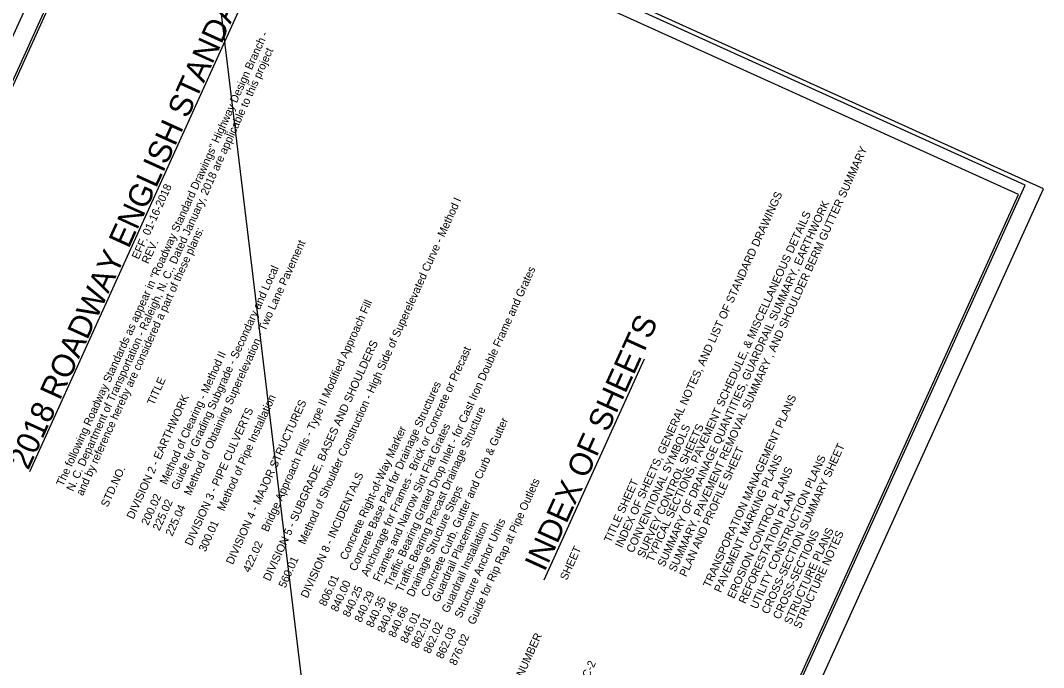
# Model space of a CAD drawing. Extents: x 1744741 to 2014229, y 466994 to 951338.
# Drawn here: x 2007510 to 2010026, y 477236 to 478827 of the extents above; entities that cross this region are included whole.
import ezdxf

# ---------------------------------------------------------------- set-up
doc = ezdxf.new("R2010")
doc.units = 0
for name, color, linetype in [('Old_Level_1', 7, 'Continuous'), ('Prop Guardrail Anchor Unit CELL', 7, 'Continuous'), ('Sheet Data Text CELL', 7, 'Continuous'), ('Sheet Plan CELL', 7, 'Continuous'), ('Sheet Plot Border Inside CELL', 7, 'Continuous'), ('Sheet Plot Border Outside CELL', 7, 'Continuous'), ('Sheet Sticker Preliminary CELL', 7, 'Continuous')]:
    doc.layers.add(name, color=color, linetype=linetype)

msp = doc.modelspace()

# ---------------------------------------------------------------- linework, layer by layer
at = {"layer": 'Old_Level_1'}
for p, q in [((2007533.4, 477718), (2008139.4, 479055)), ((2008798.2, 477452.1), (2009044.4, 477995.4))]:
    msp.add_line(p, q, dxfattribs=at)
at = {"layer": 'Prop Guardrail Anchor Unit CELL'}
msp.add_line((2008573.3, 474121.5), (2007740.2, 481039.5), dxfattribs=at)
at = {"layer": 'Sheet Plan CELL'}
msp.add_lwpolyline([(2007812, 479374.1), (2006418.7, 476300.1), (2008570.5, 475324.8), (2009963.8, 478398.8)], close=True, dxfattribs=at)
at = {"layer": 'Sheet Plot Border Inside CELL'}
msp.add_lwpolyline([(2008433, 475007.9), (2009980.5, 478422.1), (2007818.5, 479402), (2006271, 475987.9)], close=True, dxfattribs=at)
at = {"layer": 'Sheet Plot Border Outside CELL'}
msp.add_lwpolyline([(2008462, 474962.7), (2010025.7, 478412.7), (2007781.7, 479429.8), (2006218, 475979.8)], close=True, dxfattribs=at)

# ---------------------------------------------------------------- texts
at = {"layer": 'Old_Level_1'}
for s, height, p in [('422.02    Bridge Approach Fills - Type II Modified Approach Fill', 19.688, (2008073.7, 477468.1)), ('INDEX OF SHEETS', 56.25, (2008799, 477469.8)), ('DIVISION 4 - MAJOR STRUCTURES', 19.688, (2008032.4, 477487.7))]:
    msp.add_text(s, height=height, rotation=65.6171, dxfattribs=at).set_placement(p)
at = {"layer": 'Sheet Data Text CELL'}
for s, p in [('SUMMARY, PAVEMENT REMOVAL SUMMARY , AND SHOULDER BERM GUTTER SUMMARY', (2009120.8, 477469.4)), ('INDEX OF SHEETS, GENERAL NOTES, AND LIST OF STANDARD DRAWINGS', (2008989.3, 477529)), ('SUMMARY OF DRAINAGE QUANTITIES, GUARDRAIL SUMMARY, EARTHWORK ', (2009093.3, 477481.8)), ('TYPICAL SECTIONS, PAVEMENT SCHEDULE, & MISCELLANEOUS DETAILS', (2009065.5, 477494.4)), ('TRANSPORATION MANAGEMENT PLANS', (2009205.5, 477431)), ('CONVENTIONAL SYMBOLS ', (2009016.8, 477516.5)), ('SURVEY CONTROL SHEETS', (2009043.5, 477504.4)), ('PLAN AND PROFILE SHEET', (2009147.1, 477457.5)), ('CROSS-SECTION SUMMARY SHEET', (2009349.2, 477365.9)), ('PAVEMENT MARKING PLANS', (2009232.4, 477418.8)), ('UTILITY CONSTRUCTION PLANS', (2009321.5, 477378.4)), ('EROSION CONTROL PLANS', (2009264.8, 477404.1)), ('TITLE SHEET', (2008961.8, 477541.5)), ('REFORESTATION PLAN', (2009292.8, 477391.4)), ('STRUCTURE PLANS', (2009404.5, 477340.8)), ('CROSS-SECTIONS', (2009377, 477353.2)), ('STRUCTURE NOTES', (2009427.8, 477330.2)), ('SHEET NUMBER                    SHEET   ', (2008706.8, 477125.2)), ('1C-1 THRU 1C-2', (2008842.3, 477063.8))]:
    msp.add_text(s, height=19.688, rotation=65.6171, dxfattribs=at).set_placement(p)
at = {"layer": 'Sheet Sticker Preliminary CELL'}
for s, height, p in [('2018 ROADWAY ENGLISH STANDARD DRAWINGS', 56.25, (2007529.5, 477719.6)), ('The following Roadway Standards as appear in "Roadway Standard Drawings" Highway Design Branch -', 19.688, (2007615, 477680.2)), ('N. C. Department of Transportation - Raleigh, N. C., Dated January, 2018 are applicable to this project', 19.6877, (2007640, 477667.6)), ('                                                      EFF. 01-16-2018', 19.688, (2007637.7, 477878.3)), ('560.01     Method of Shoulder Construction - High Side of Superelevated Curve - Method I', 19.688, (2008161.5, 477430.3)), ('and by reference hereby are considered a part of these plans:', 19.688, (2007663.8, 477656.8)), ('                                                      REV. ', 19.688, (2007661.7, 477867)), ('225.04    Method of Obtaining Superelevation - Two Lane Pavement', 19.688, (2007883.6, 477557.5)), ('225.02    Guide for Grading Subgrade - Secondary and Local', 19.688, (2007852.1, 477570.9)), ('840.35    Traffic Bearing Grated Drop Inlet - for Cast Iron Double Frame and Grates', 19.688, (2008376.6, 477332.8)), ('DIVISION 5 - SUBGRADE, BASES AND SHOULDERS', 19.688, (2008123.6, 477447.2)), ('200.02    Method of Clearing - Method II', 19.688, (2007824.2, 477584.2)), ('840.25    Anchorage for Frames - Brick or Concrete or Precast', 19.688, (2008319, 477358.5)), ('STD.NO.                       TITLE', 19.688, (2007724.8, 477628.8)), ('840.00    Concrete Base Pad for Drainage Structures', 19.688, (2008289.9, 477371.5)), ('DIVISION 2 - EARTHWORK', 19.688, (2007788, 477599.3)), ('300.01    Method of Pipe Installation ', 19.688, (2007965.3, 477519.1)), ('DIVISION 3 - PIPE CULVERTS', 19.688, (2007931.2, 477533.8)), ('840.46    Traffic Bearing Precast Drainage Structure', 19.688, (2008404.2, 477320)), ('806.01      Concrete Right-of-Way Marker', 19.688, (2008260.8, 477385.5)), ('840.29    Frames and Narrow Slot Flat Grates', 19.688, (2008348, 477345.6)), ('846.01      Concrete Curb, Gutter and Curb & Gutter', 19.688, (2008460.6, 477294.5)), ('DIVISION 8 - INCIDENTALS', 19.688, (2008216, 477405.3)), ('840.66    Drainage Structure Steps', 19.688, (2008431.3, 477308.2)), ('876.02    Guide for Rip Rap at Pipe Outlets', 19.688, (2008581.1, 477239.8)), ('862.01      Guardrail Placement', 19.688, (2008487.4, 477281.7)), ('862.03    Structure Anchor Units', 19.688, (2008548.8, 477255.9)), ('862.02    Guardrail Installation', 19.688, (2008517.2, 477268.9))]:
    msp.add_text(s, height=height, rotation=65.6171, dxfattribs=at).set_placement(p)

doc.saveas('drawing.dxf')
